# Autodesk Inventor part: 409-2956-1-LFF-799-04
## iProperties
Created: 2010-11
Part Number: 409-2956-1-LFF-799-04
Material: 3/4" OD TUBE - SS
Document SubType Name: Modeling
Designer: S. Boerckel
Engineer: Steve Boerckel
Mass: 731.966 g
Surface Area: 1099.2 cm^2
Volume: 90.5898 cm^3
Density: 8.08 g/cm^3
Description: DRAIN TUBING
Length: 40.702 in
Author: S. Boerckel
Revision Number: 0
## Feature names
1. Sweep2
